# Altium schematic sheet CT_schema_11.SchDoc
size 274 x 160 mm
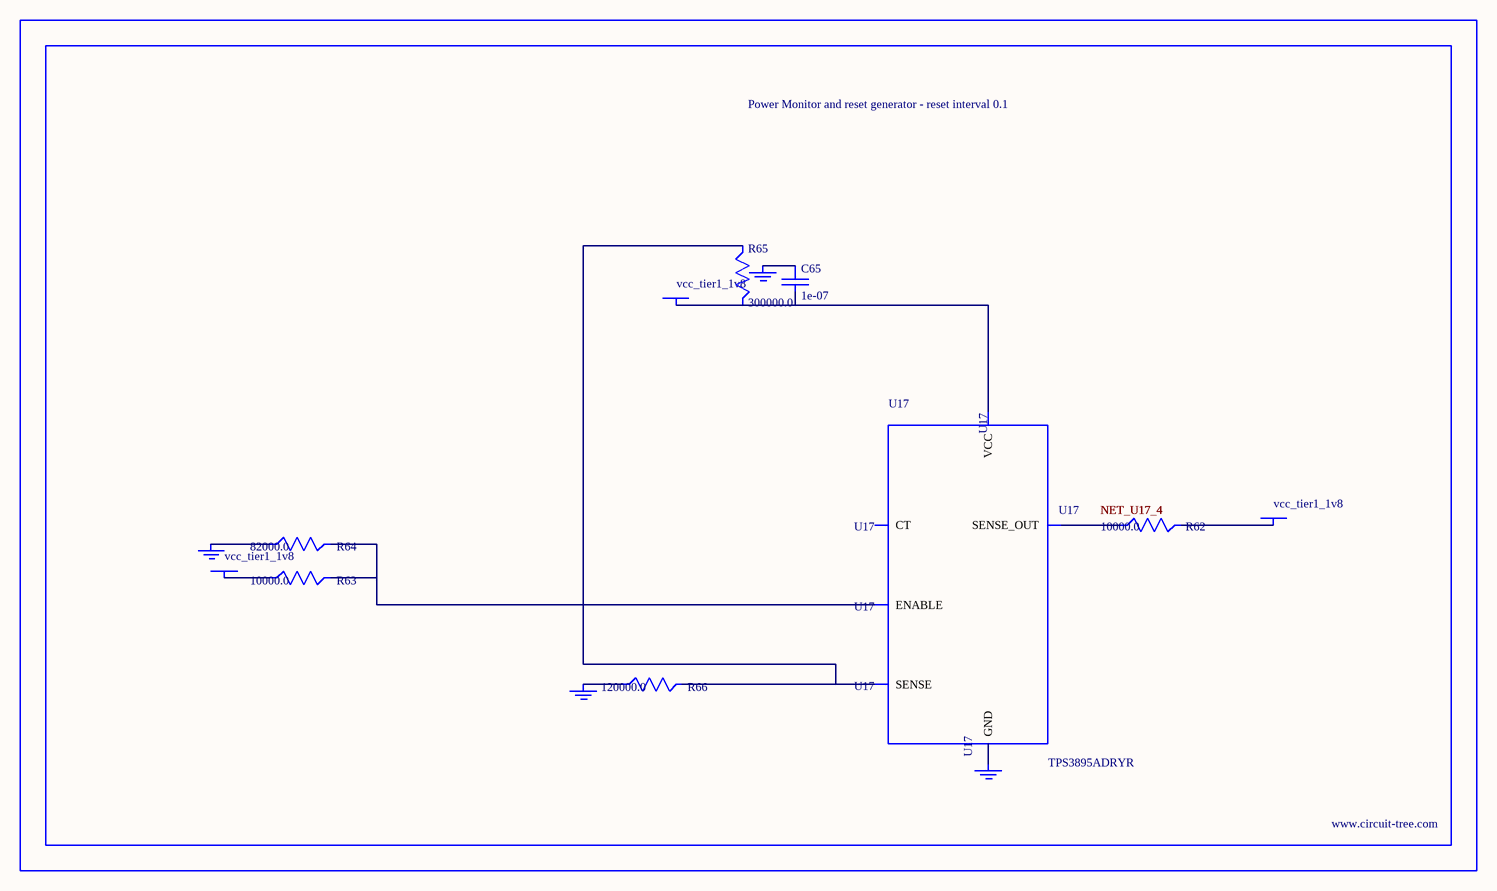
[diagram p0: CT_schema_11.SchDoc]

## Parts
BORDER10  (no value)
C65  1e-07  [C0402]
GND_INSTANCE_10_0  (no value)
GND_INSTANCE_10_1  (no value)
GND_INSTANCE_10_2  (no value)
GND_INSTANCE_10_3  (no value)
POWER_INSTANCE_10_0  vcc_tier1_1v8
POWER_INSTANCE_10_1  vcc_tier1_1v8
POWER_INSTANCE_10_2  vcc_tier1_1v8
R62  10000.0  [R0603]
R63  10000.0  [R0603]
R64  82000.0  [R0603]
R65  300000.0  [R0603]
R66  120000.0  [R0603]
U17  TPS3895ADRYR  [SON-6]

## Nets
NetC65_1: C65.1 GND_INSTANCE_10_2.0(GND)
NetC65_2: C65.2 POWER_INSTANCE_10_2.0(PWR) R65.2 U17.6(VCC)
NetGND_INSTANCE_10_0_0: GND_INSTANCE_10_0.0(GND) R64.1
NetGND_INSTANCE_10_1_0: GND_INSTANCE_10_1.0(GND) R66.1
NetGND_INSTANCE_10_3_0: GND_INSTANCE_10_3.0(GND) U17.2(GND)
NetPOWER_INSTANCE_10_0_0: POWER_INSTANCE_10_0.0(PWR) R63.1
NetPOWER_INSTANCE_10_1_0: POWER_INSTANCE_10_1.0(PWR) R62.2
NetR62_1: R62.1 U17.4(SENSE_OUT)
NetR63_2: R63.2 R64.2 U17.1(ENABLE)
NetR65_1: R65.1 R66.2 U17.3(SENSE)

Not connected (* = marked no-connect by the designer): U17 5(CT)

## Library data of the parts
BORDER10 = BORDER_PAGE10
C65 = C0402C104K3RACTU
GND_INSTANCE_10_0-GND_INSTANCE_10_3 = GND
POWER_INSTANCE_10_0-POWER_INSTANCE_10_2 = PWR
R62 R63 = RC0603JR-0710KL
R64 = RC0603JR-0782KL
R65 = RC0603JR-07300KL
R66 = RC0603JR-07120KL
